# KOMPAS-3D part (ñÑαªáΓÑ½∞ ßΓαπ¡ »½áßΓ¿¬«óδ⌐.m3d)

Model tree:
1. Эскиз:1
2. Операция выдавливания:1
     Расстояние 1 = 30
3. Эскиз:2
4. Операция выдавливания:2
     Расстояние 1 = 20; Расстояние 2 = 30
5. Скругление:1
     Радиус = 3
6. Эскиз:3
7. Вырезать элемент выдавливания:1
     Расстояние 1 = 20
8. Эскиз:4
9. Вырезать элемент выдавливания:2
     Расстояние 1 = 4; Угол 1 = 32
10. Эскиз:5
11. Вырезать элемент выдавливания:3
     Расстояние 2 = 20; Расстояние 1 = 94
12. Эскиз:6
13. Вырезать элемент выдавливания:4
     Расстояние 1 = 40
